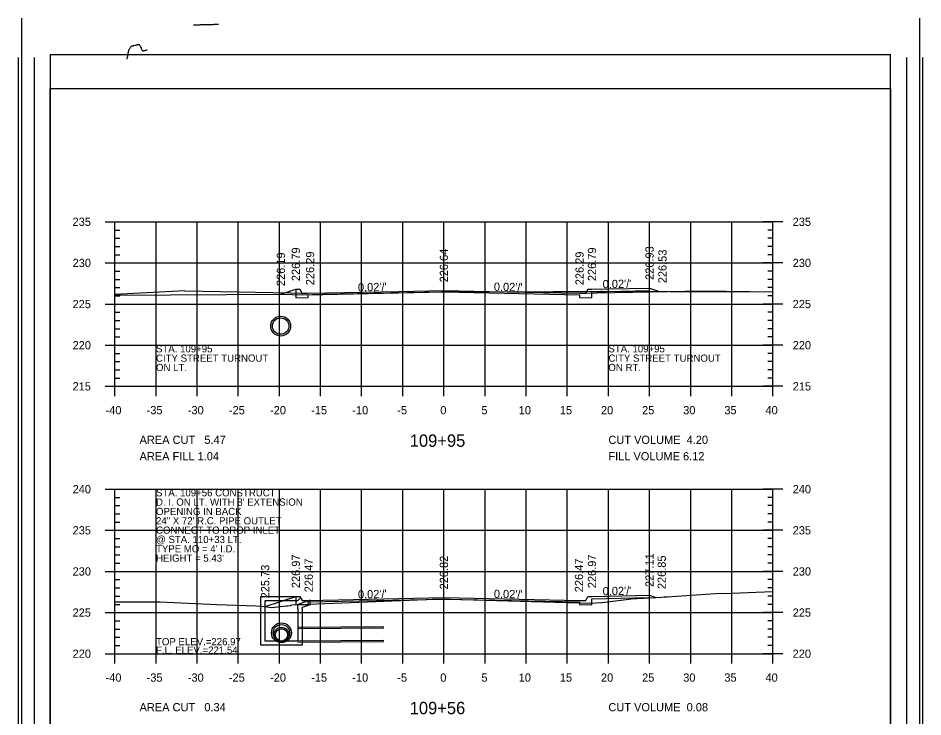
# Model space of a CAD drawing. Extents: x 1367903 to 1373764, y 376865 to 382130.
# Drawn here: x 1372116.6 to 1372336.6, y 377450.5 to 377620.4 of the extents above; entities that cross this region are included whole.
import ezdxf

# ---------------------------------------------------------------- set-up
doc = ezdxf.new("R2010")
doc.units = 0
for name, color, linetype in [('R_Axis', 7, 'Continuous'), ('R_Axis Annot', 7, 'Continuous'), ('R_Border', 7, 'Continuous'), ('R_Border PE', 7, 'Continuous'), ('R_Draft', 7, 'Continuous'), ('R_Drive', 7, 'Continuous'), ('R_Exist Surface', 7, 'Continuous'), ('R_Fin Surface', 7, 'Continuous'), ('R_Fin Surface Annot', 7, 'Continuous'), ('R_Grid', 7, 'Continuous'), ('R_Water', 7, 'Continuous'), ('R_Water Annot', 7, 'Continuous')]:
    doc.layers.add(name, color=color, linetype=linetype)

msp = doc.modelspace()

# ---------------------------------------------------------------- linework, layer by layer
for p, q in [((1372175.66, 377479.78), (1372185.16, 377479.78)), ((1372175.66, 377476.78), (1372175.66, 377479.78)), ((1372176.66, 377476.78), (1372176.66, 377478.78)), ((1372176.66, 377478.78), (1372184.66, 377478.78)), ((1372185.32, 377479.45), (1372184.66, 377478.78)), ((1372187.66, 377478.82), (1372184.66, 377477.78)), ((1372185.32, 377479.45), (1372185.16, 377479.78)), ((1372184.66, 377476.78), (1372184.66, 377477.78)), ((1372187.66, 377477.76), (1372185.66, 377477.07)), ((1372185.66, 377476.78), (1372185.66, 377477.07))]:
    msp.add_line(p, q)
for points in [[(1372184.16, 377554.42), (1372184.16, 377553.75), (1372184.16, 377553.75), (1372184.16, 377552.39), (1372187.16, 377552.45), (1372187.16, 377553.12), (1372220.16, 377553.78), (1372253.16, 377553.12), (1372253.16, 377552.45), (1372256.16, 377552.39), (1372256.16, 377553.83), (1372270.16, 377554.11), (1372270.16, 377554.7)], [(1372184.16, 377479.78), (1372184.16, 377479.11), (1372184.16, 377479.11), (1372184.16, 377477.75), (1372187.16, 377477.81), (1372187.16, 377478.47), (1372220.16, 377479.13), (1372253.16, 377478.47), (1372253.16, 377477.81), (1372256.16, 377477.75), (1372256.16, 377479.19), (1372270.16, 377479.47), (1372270.16, 377480.06)], [(1372187.66, 377477.76), (1372187.66, 377478.82)]]:
    msp.add_lwpolyline(points)
at = {"layer": 'R_Axis'}
for p, q in [((1372137.76, 377570.84), (1372142.56, 377570.84)), ((1372140.16, 377530.84), (1372140.16, 377570.84)), ((1372302.56, 377570.84), (1372297.76, 377570.84)), ((1372300.16, 377530.84), (1372300.16, 377570.84)), ((1372140.16, 377568.84), (1372141.36, 377568.84)), ((1372140.16, 377566.84), (1372141.36, 377566.84)), ((1372300.16, 377568.84), (1372298.96, 377568.84)), ((1372300.16, 377566.84), (1372298.96, 377566.84)), ((1372140.16, 377564.84), (1372141.36, 377564.84)), ((1372300.16, 377564.84), (1372298.96, 377564.84)), ((1372140.16, 377562.84), (1372141.36, 377562.84)), ((1372300.16, 377562.84), (1372298.96, 377562.84)), ((1372137.76, 377560.84), (1372142.56, 377560.84)), ((1372302.56, 377560.84), (1372297.76, 377560.84)), ((1372140.16, 377558.84), (1372141.36, 377558.84)), ((1372300.16, 377558.84), (1372298.96, 377558.84)), ((1372140.16, 377556.84), (1372141.36, 377556.84)), ((1372300.16, 377556.84), (1372298.96, 377556.84)), ((1372140.16, 377554.84), (1372141.36, 377554.84)), ((1372300.16, 377554.84), (1372298.96, 377554.84)), ((1372140.16, 377552.84), (1372141.36, 377552.84)), ((1372300.16, 377552.84), (1372298.96, 377552.84)), ((1372137.76, 377550.84), (1372142.56, 377550.84)), ((1372302.56, 377550.84), (1372297.76, 377550.84)), ((1372140.16, 377548.84), (1372141.36, 377548.84)), ((1372300.16, 377548.84), (1372298.96, 377548.84)), ((1372140.16, 377546.84), (1372141.36, 377546.84)), ((1372140.16, 377544.84), (1372141.36, 377544.84)), ((1372300.16, 377546.84), (1372298.96, 377546.84)), ((1372300.16, 377544.84), (1372298.96, 377544.84)), ((1372140.16, 377542.84), (1372141.36, 377542.84)), ((1372300.16, 377542.84), (1372298.96, 377542.84)), ((1372137.76, 377540.84), (1372142.56, 377540.84)), ((1372302.56, 377540.84), (1372297.76, 377540.84)), ((1372140.16, 377538.84), (1372141.36, 377538.84)), ((1372300.16, 377538.84), (1372298.96, 377538.84)), ((1372140.16, 377536.84), (1372141.36, 377536.84)), ((1372300.16, 377536.84), (1372298.96, 377536.84)), ((1372140.16, 377534.84), (1372141.36, 377534.84)), ((1372300.16, 377534.84), (1372298.96, 377534.84)), ((1372140.16, 377528.44), (1372140.16, 377533.24)), ((1372140.16, 377532.84), (1372141.36, 377532.84)), ((1372150.16, 377528.44), (1372150.16, 377533.24)), ((1372160.16, 377528.44), (1372160.16, 377533.24)), ((1372170.16, 377528.44), (1372170.16, 377533.24)), ((1372180.16, 377528.44), (1372180.16, 377533.24)), ((1372190.16, 377528.44), (1372190.16, 377533.24)), ((1372200.16, 377528.44), (1372200.16, 377533.24)), ((1372210.16, 377528.44), (1372210.16, 377533.24)), ((1372220.16, 377528.44), (1372220.16, 377533.24)), ((1372230.16, 377528.44), (1372230.16, 377533.24)), ((1372240.16, 377528.44), (1372240.16, 377533.24)), ((1372250.16, 377528.44), (1372250.16, 377533.24)), ((1372260.16, 377528.44), (1372260.16, 377533.24)), ((1372270.16, 377528.44), (1372270.16, 377533.24)), ((1372280.16, 377528.44), (1372280.16, 377533.24)), ((1372290.16, 377528.44), (1372290.16, 377533.24)), ((1372300.16, 377532.84), (1372298.96, 377532.84)), ((1372300.16, 377528.44), (1372300.16, 377533.24)), ((1372137.76, 377530.84), (1372142.56, 377530.84)), ((1372140.16, 377530.84), (1372300.16, 377530.84)), ((1372302.56, 377530.84), (1372297.76, 377530.84)), ((1372137.76, 377505.84), (1372142.56, 377505.84)), ((1372140.16, 377465.84), (1372140.16, 377505.84)), ((1372302.56, 377505.84), (1372297.76, 377505.84)), ((1372300.16, 377465.84), (1372300.16, 377505.84)), ((1372140.16, 377503.84), (1372141.36, 377503.84)), ((1372300.16, 377503.84), (1372298.96, 377503.84)), ((1372140.16, 377501.84), (1372141.36, 377501.84)), ((1372300.16, 377501.84), (1372298.96, 377501.84)), ((1372140.16, 377499.84), (1372141.36, 377499.84)), ((1372300.16, 377499.84), (1372298.96, 377499.84)), ((1372140.16, 377497.84), (1372141.36, 377497.84)), ((1372300.16, 377497.84), (1372298.96, 377497.84)), ((1372137.76, 377495.84), (1372142.56, 377495.84)), ((1372302.56, 377495.84), (1372297.76, 377495.84)), ((1372140.16, 377493.84), (1372141.36, 377493.84)), ((1372300.16, 377493.84), (1372298.96, 377493.84)), ((1372140.16, 377491.84), (1372141.36, 377491.84)), ((1372140.16, 377489.84), (1372141.36, 377489.84)), ((1372300.16, 377491.84), (1372298.96, 377491.84)), ((1372300.16, 377489.84), (1372298.96, 377489.84)), ((1372140.16, 377487.84), (1372141.36, 377487.84)), ((1372300.16, 377487.84), (1372298.96, 377487.84)), ((1372137.76, 377485.84), (1372142.56, 377485.84)), ((1372302.56, 377485.84), (1372297.76, 377485.84)), ((1372140.16, 377483.84), (1372141.36, 377483.84)), ((1372300.16, 377483.84), (1372298.96, 377483.84)), ((1372140.16, 377481.84), (1372141.36, 377481.84)), ((1372300.16, 377481.84), (1372298.96, 377481.84)), ((1372140.16, 377479.84), (1372141.36, 377479.84)), ((1372300.16, 377479.84), (1372298.96, 377479.84)), ((1372140.16, 377477.84), (1372141.36, 377477.84)), ((1372300.16, 377477.84), (1372298.96, 377477.84)), ((1372137.76, 377475.84), (1372142.56, 377475.84)), ((1372302.56, 377475.84), (1372297.76, 377475.84)), ((1372140.16, 377473.84), (1372141.36, 377473.84)), ((1372300.16, 377473.84), (1372298.96, 377473.84)), ((1372140.16, 377471.84), (1372141.36, 377471.84)), ((1372300.16, 377471.84), (1372298.96, 377471.84)), ((1372140.16, 377469.84), (1372141.36, 377469.84)), ((1372140.16, 377463.44), (1372140.16, 377468.24)), ((1372140.16, 377467.84), (1372141.36, 377467.84)), ((1372150.16, 377463.44), (1372150.16, 377468.24)), ((1372160.16, 377463.44), (1372160.16, 377468.24)), ((1372170.16, 377463.44), (1372170.16, 377468.24)), ((1372180.16, 377463.44), (1372180.16, 377468.24)), ((1372190.16, 377463.44), (1372190.16, 377468.24)), ((1372200.16, 377463.44), (1372200.16, 377468.24)), ((1372210.16, 377463.44), (1372210.16, 377468.24)), ((1372220.16, 377463.44), (1372220.16, 377468.24)), ((1372230.16, 377463.44), (1372230.16, 377468.24)), ((1372240.16, 377463.44), (1372240.16, 377468.24)), ((1372250.16, 377463.44), (1372250.16, 377468.24)), ((1372260.16, 377463.44), (1372260.16, 377468.24)), ((1372270.16, 377463.44), (1372270.16, 377468.24)), ((1372280.16, 377463.44), (1372280.16, 377468.24)), ((1372290.16, 377463.44), (1372290.16, 377468.24)), ((1372300.16, 377469.84), (1372298.96, 377469.84)), ((1372300.16, 377467.84), (1372298.96, 377467.84)), ((1372300.16, 377463.44), (1372300.16, 377468.24)), ((1372137.76, 377465.84), (1372142.56, 377465.84)), ((1372140.16, 377465.84), (1372300.16, 377465.84)), ((1372302.56, 377465.84), (1372297.76, 377465.84))]:
    msp.add_line(p, q, dxfattribs=at)
at = {"layer": 'R_Border'}
for p, q in [((1372117.43, 377620.35), (1372117.43, 377279.12)), ((1372335.82, 377620.35), (1372335.82, 377279.12)), ((1372124.46, 377611.47), (1372328.78, 377611.47)), ((1372124.46, 377611.47), (1372124.46, 377280.59)), ((1372328.78, 377280.59), (1372328.78, 377611.47))]:
    msp.add_line(p, q, dxfattribs=at)
at = {"layer": 'R_Border PE'}
for p, q in [((1372116.63, 377610.76), (1372116.63, 377288.8)), ((1372120.54, 377610.76), (1372120.54, 377288.8)), ((1372332.71, 377288.8), (1372332.71, 377610.76)), ((1372336.63, 377288.8), (1372336.63, 377610.76)), ((1372124.46, 377603.25), (1372328.78, 377603.25)), ((1372124.46, 377288.8), (1372124.46, 377603.25)), ((1372328.78, 377603.25), (1372328.78, 377288.8))]:
    msp.add_line(p, q, dxfattribs=at)
for points in [[(1372161.32, 377618.69), (1372161.26, 377618.69), (1372160.99, 377618.68), (1372160.86, 377618.68), (1372160.79, 377618.67), (1372160.63, 377618.67), (1372160.27, 377618.66), (1372159.94, 377618.65), (1372159.31, 377618.63)], [(1372161.77, 377618.7), (1372161.32, 377618.69)], [(1372165.33, 377618.79), (1372164.99, 377618.78), (1372164.79, 377618.78), (1372164.63, 377618.77), (1372164.4, 377618.76), (1372164.24, 377618.76), (1372164.05, 377618.75), (1372163.8, 377618.75), (1372163.61, 377618.74), (1372163.33, 377618.73), (1372163.23, 377618.73), (1372163.18, 377618.73), (1372162.96, 377618.72), (1372162.85, 377618.72), (1372162.63, 377618.71), (1372162.55, 377618.72), (1372162.13, 377618.7), (1372161.88, 377618.7), (1372161.77, 377618.7)], [(1372148.02, 377612.54), (1372148, 377612.55), (1372147.98, 377612.55), (1372147.96, 377612.55), (1372147.94, 377612.55), (1372147.91, 377612.55), (1372147.88, 377612.55), (1372147.86, 377612.55), (1372147.72, 377612.51), (1372147.6, 377612.48), (1372147.33, 377612.41), (1372147.11, 377612.36), (1372147.09, 377612.35), (1372147.07, 377612.35), (1372147.04, 377612.34), (1372147.03, 377612.34), (1372147.02, 377612.35), (1372147, 377612.35), (1372146.98, 377612.36), (1372146.95, 377612.38), (1372146.93, 377612.39), (1372146.91, 377612.4), (1372146.9, 377612.42), (1372146.88, 377612.45), (1372146.87, 377612.47), (1372146.85, 377612.5), (1372146.83, 377612.55), (1372146.73, 377612.76), (1372146.62, 377613), (1372146.52, 377613.23), (1372146.51, 377613.26), (1372146.5, 377613.28), (1372146.46, 377613.34), (1372146.43, 377613.39), (1372146.31, 377613.57), (1372146.23, 377613.69), (1372146.2, 377613.74), (1372146.18, 377613.76), (1372146.17, 377613.78), (1372146.14, 377613.81), (1372146.13, 377613.83), (1372146.11, 377613.84), (1372146.1, 377613.85), (1372146.07, 377613.87), (1372146.06, 377613.87), (1372146.03, 377613.88), (1372146, 377613.88), (1372145.99, 377613.88), (1372145.95, 377613.88), (1372145.84, 377613.86), (1372145.67, 377613.82), (1372145.48, 377613.77), (1372145.33, 377613.74), (1372145.23, 377613.72), (1372145.09, 377613.69), (1372144.97, 377613.66), (1372144.79, 377613.63), (1372144.57, 377613.58), (1372144.52, 377613.57), (1372144.4, 377613.54), (1372144.29, 377613.52), (1372144.25, 377613.51), (1372144.22, 377613.5), (1372144.2, 377613.5), (1372144.18, 377613.49), (1372144.17, 377613.49), (1372144.15, 377613.47), (1372144.13, 377613.46), (1372144.11, 377613.44), (1372144.08, 377613.42), (1372144.05, 377613.39), (1372144.03, 377613.35), (1372144, 377613.31), (1372143.96, 377613.26), (1372143.9, 377613.16), (1372143.8, 377613.02), (1372143.72, 377612.89), (1372143.63, 377612.75), (1372143.58, 377612.67), (1372143.54, 377612.62), (1372143.5, 377612.55), (1372143.49, 377612.54), (1372143.48, 377612.52), (1372143.47, 377612.5), (1372143.47, 377612.48), (1372143.46, 377612.46), (1372143.46, 377612.44), (1372143.45, 377612.42), (1372143.44, 377612.39), (1372143.44, 377612.37), (1372143.43, 377612.35), (1372143.43, 377612.33), (1372143.41, 377612.24), (1372143.37, 377612), (1372143.33, 377611.76), (1372143.31, 377611.65), (1372143.22, 377611.18), (1372143.2, 377611.04), (1372143.16, 377610.84), (1372143.1, 377610.54), (1372143.07, 377610.39)]]:
    msp.add_lwpolyline(points, dxfattribs=at)
at = {"layer": 'R_Drive'}
for p, q in [((1372157.16, 377554.05), (1372140.16, 377553.17)), ((1372157.16, 377554.05), (1372187.16, 377553.45)), ((1372253.16, 377553.45), (1372283.15, 377554.05)), ((1372283.15, 377554.05), (1372300.16, 377553.83))]:
    msp.add_line(p, q, dxfattribs=at)
at = {"layer": 'R_Exist Surface'}
for points in [[(1372140.16, 377553.03), (1372180.83, 377553.21), (1372181.09, 377553.22), (1372185.43, 377553.11), (1372190.86, 377553.25), (1372219.5, 377553.83), (1372220, 377553.84), (1372220.29, 377553.84), (1372246.83, 377553.86), (1372254.98, 377553.87), (1372254.98, 377553.87), (1372255.01, 377553.87), (1372258.35, 377553.95), (1372258.46, 377553.95), (1372258.54, 377553.94), (1372275.18, 377553.89), (1372300.16, 377553.8)], [(1372140.16, 377478.42), (1372142.21, 377478.42), (1372151.12, 377478.47), (1372164.96, 377477.84), (1372174.4, 377477.45), (1372175.86, 377477.39), (1372178.22, 377477.1), (1372181.85, 377477.45), (1372182.14, 377477.46), (1372182.86, 377477.52), (1372183.2, 377477.71), (1372215.73, 377479.05), (1372218.67, 377479.2), (1372221.75, 377479.1), (1372255.67, 377478.09), (1372258.48, 377478.32), (1372258.67, 377478.31), (1372265.09, 377479.07), (1372265.71, 377479.17), (1372273.15, 377479.62), (1372273.73, 377479.66), (1372274.42, 377479.69), (1372286.21, 377480.45), (1372290.1, 377480.53), (1372300.16, 377480.99)]]:
    msp.add_lwpolyline(points, dxfattribs=at)
at = {"layer": 'R_Fin Surface'}
for points in [[(1372180.51, 377553.21), (1372184.16, 377554.42), (1372185.16, 377554.42), (1372185.66, 377553.42), (1372187.16, 377553.45), (1372209.16, 377553.89), (1372220.16, 377554.11), (1372231.16, 377553.89), (1372253.16, 377553.45), (1372254.66, 377553.42), (1372255.16, 377554.42), (1372256.16, 377554.42), (1372260.16, 377554.5), (1372270.16, 377554.7), (1372272.56, 377553.9)], [(1372176.7, 377477.29), (1372184.16, 377479.78), (1372185.16, 377479.78), (1372185.66, 377478.78), (1372187.16, 377478.81), (1372209.16, 377479.25), (1372220.16, 377479.47), (1372231.16, 377479.25), (1372253.16, 377478.81), (1372254.66, 377478.78), (1372255.16, 377479.78), (1372256.16, 377479.78), (1372260.16, 377479.86), (1372270.16, 377480.06), (1372271.72, 377479.54)]]:
    msp.add_lwpolyline(points, dxfattribs=at)
at = {"layer": 'R_Grid'}
for p, q in [((1372140.16, 377570.84), (1372300.16, 377570.84)), ((1372140.16, 377530.84), (1372140.16, 377570.84)), ((1372150.16, 377530.84), (1372150.16, 377570.84)), ((1372160.16, 377530.84), (1372160.16, 377570.84)), ((1372170.16, 377530.84), (1372170.16, 377570.84)), ((1372180.16, 377530.84), (1372180.16, 377570.84)), ((1372190.16, 377530.84), (1372190.16, 377570.84)), ((1372200.16, 377530.84), (1372200.16, 377570.84)), ((1372210.16, 377530.84), (1372210.16, 377570.84)), ((1372220.16, 377530.84), (1372220.16, 377570.84)), ((1372230.16, 377530.84), (1372230.16, 377570.84)), ((1372240.16, 377530.84), (1372240.16, 377570.84)), ((1372250.16, 377530.84), (1372250.16, 377570.84)), ((1372260.16, 377530.84), (1372260.16, 377570.84)), ((1372270.16, 377530.84), (1372270.16, 377570.84)), ((1372280.16, 377530.84), (1372280.16, 377570.84)), ((1372290.16, 377530.84), (1372290.16, 377570.84)), ((1372300.16, 377530.84), (1372300.16, 377570.84)), ((1372140.16, 377560.84), (1372300.16, 377560.84)), ((1372140.16, 377550.84), (1372300.16, 377550.84)), ((1372140.16, 377540.84), (1372300.16, 377540.84)), ((1372140.16, 377530.84), (1372300.16, 377530.84)), ((1372140.16, 377505.84), (1372300.16, 377505.84)), ((1372140.16, 377465.84), (1372140.16, 377505.84)), ((1372150.16, 377465.84), (1372150.16, 377505.84)), ((1372160.16, 377465.84), (1372160.16, 377505.84)), ((1372170.16, 377465.84), (1372170.16, 377505.84)), ((1372180.16, 377465.84), (1372180.16, 377505.84)), ((1372190.16, 377465.84), (1372190.16, 377505.84)), ((1372200.16, 377465.84), (1372200.16, 377505.84)), ((1372210.16, 377465.84), (1372210.16, 377505.84)), ((1372220.16, 377465.84), (1372220.16, 377505.84)), ((1372230.16, 377465.84), (1372230.16, 377505.84)), ((1372240.16, 377465.84), (1372240.16, 377505.84)), ((1372250.16, 377465.84), (1372250.16, 377505.84)), ((1372260.16, 377465.84), (1372260.16, 377505.84)), ((1372270.16, 377465.84), (1372270.16, 377505.84)), ((1372280.16, 377465.84), (1372280.16, 377505.84)), ((1372290.16, 377465.84), (1372290.16, 377505.84)), ((1372300.16, 377465.84), (1372300.16, 377505.84)), ((1372140.16, 377495.84), (1372300.16, 377495.84)), ((1372140.16, 377485.84), (1372300.16, 377485.84)), ((1372140.16, 377475.84), (1372300.16, 377475.84)), ((1372140.16, 377465.84), (1372300.16, 377465.84))]:
    msp.add_line(p, q, dxfattribs=at)
at = {"layer": 'R_Water'}
for p, q in [((1372180.48, 377547.92), (1372180.48, 377547.87)), ((1372180.48, 377547.5), (1372180.48, 377547.45)), ((1372180.48, 377543.5), (1372180.48, 377543.45)), ((1372180.48, 377543.08), (1372180.48, 377543.03)), ((1372205.54, 377472.38), (1372184.61, 377472.25)), ((1372205.54, 377472.04), (1372184.61, 377471.92)), ((1372205.54, 377469.04), (1372184.61, 377468.92)), ((1372205.54, 377468.71), (1372184.61, 377468.58))]:
    msp.add_line(p, q, dxfattribs=at)
for points in [[(1372185.66, 377476.78), (1372185.66, 377467.92), (1372180.66, 377467.92), (1372175.66, 377467.92), (1372175.66, 377476.78)], [(1372184.66, 377476.78), (1372184.66, 377468.92), (1372180.66, 377468.92), (1372176.66, 377468.92), (1372176.66, 377476.78)]]:
    msp.add_lwpolyline(points, dxfattribs=at)
for centre, radius in [((1372180.48, 377545.48), 2.42), ((1372180.48, 377545.48), 2), ((1372180.66, 377470.92), 2.42), ((1372180.66, 377470.92), 2), ((1372180.66, 377470.42), 1.83), ((1372180.66, 377470.42), 1.5)]:
    msp.add_circle(centre, radius, dxfattribs=at)

# ---------------------------------------------------------------- texts
at = {"layer": 'R_Axis Annot'}
for s, height, p in [('235', 2, (1372129.87, 377569.84)), ('235', 2, (1372304.96, 377569.84)), ('230', 2, (1372129.88, 377559.84)), ('230', 2, (1372304.96, 377559.84)), ('225', 2, (1372129.87, 377549.84)), ('225', 2, (1372304.96, 377549.84)), ('220', 2, (1372129.88, 377539.84)), ('220', 2, (1372304.96, 377539.84)), ('215', 2, (1372129.87, 377529.84)), ('215', 2, (1372304.96, 377529.84)), ('-40', 2, (1372137.89, 377524.04)), ('-35', 2, (1372147.88, 377524.04)), ('-30', 2, (1372157.89, 377524.04)), ('-25', 2, (1372167.88, 377524.04)), ('-20', 2, (1372177.89, 377524.04)), ('-15', 2, (1372187.88, 377524.04)), ('-10', 2, (1372197.89, 377524.04)), ('-5', 2, (1372208.82, 377524.04)), ('0', 2, (1372219.28, 377524.04)), ('5', 2, (1372229.28, 377524.04)), ('10', 2, (1372238.35, 377524.04)), ('15', 2, (1372248.35, 377524.04)), ('20', 2, (1372258.35, 377524.04)), ('25', 2, (1372268.35, 377524.04)), ('30', 2, (1372278.35, 377524.04)), ('35', 2, (1372288.35, 377524.04)), ('40', 2, (1372298.35, 377524.04)), ('AREA CUT   5.47', 2, (1372146.16, 377516.84)), ('109+95', 3, (1372211.86, 377516.14)), ('CUT VOLUME  4.20', 2, (1372260.16, 377516.84)), ('AREA FILL 1.04', 2, (1372146.16, 377512.84)), ('FILL VOLUME 6.12', 2, (1372260.16, 377512.84)), ('240', 2, (1372129.88, 377504.84)), ('240', 2, (1372304.96, 377504.84)), ('235', 2, (1372129.87, 377494.84)), ('235', 2, (1372304.96, 377494.84)), ('230', 2, (1372129.88, 377484.84)), ('230', 2, (1372304.96, 377484.84)), ('225', 2, (1372129.87, 377474.84)), ('225', 2, (1372304.96, 377474.84)), ('220', 2, (1372129.88, 377464.84)), ('220', 2, (1372304.96, 377464.84)), ('-40', 2, (1372137.89, 377459.04)), ('-35', 2, (1372147.88, 377459.04)), ('-30', 2, (1372157.89, 377459.04)), ('-25', 2, (1372167.88, 377459.04)), ('-20', 2, (1372177.89, 377459.04)), ('-15', 2, (1372187.88, 377459.04)), ('-10', 2, (1372197.89, 377459.04)), ('-5', 2, (1372208.82, 377459.04)), ('0', 2, (1372219.28, 377459.04)), ('5', 2, (1372229.28, 377459.04)), ('10', 2, (1372238.35, 377459.04)), ('15', 2, (1372248.35, 377459.04)), ('20', 2, (1372258.35, 377459.04)), ('25', 2, (1372268.35, 377459.04)), ('30', 2, (1372278.35, 377459.04)), ('35', 2, (1372288.35, 377459.04)), ('40', 2, (1372298.35, 377459.04)), ('AREA CUT   0.34', 2, (1372146.16, 377451.84)), ('109+56', 3, (1372211.85, 377451.14)), ('CUT VOLUME  0.08', 2, (1372260.16, 377451.84))]:
    msp.add_text(s, height=height, dxfattribs=at).set_placement(p)
at = {"layer": 'R_Draft'}
for s, p in [('STA. 109+95', (1372150.16, 377539.09)), ('STA. 109+95', (1372260.16, 377539.09)), ('CITY STREET TURNOUT', (1372150.16, 377536.82)), ('CITY STREET TURNOUT', (1372260.16, 377536.82)), ('ON LT.', (1372150.16, 377534.55)), ('ON RT.', (1372260.16, 377534.55)), ('STA. 109+56 CONSTRUCT', (1372150.16, 377504.09)), ("D. I. ON LT. WITH 8' EXTENSION", (1372150.16, 377501.82)), ('OPENING IN BACK', (1372150.16, 377499.55)), ('24" X 72\' R.C. PIPE OUTLET', (1372150.16, 377497.28)), ('CONNECT TO DROP INLET', (1372150.16, 377495.01)), ('@ STA. 110+33 LT.', (1372150.16, 377492.74)), ("TYPE MO = 4' I.D.", (1372150.16, 377490.47)), ("HEIGHT = 5.43'", (1372150.16, 377488.2))]:
    msp.add_text(s, height=1.75, dxfattribs=at).set_placement(p)
at = {"layer": 'R_Fin Surface Annot'}
for s, rotation, p in [('226.93', 90, (1372271.16, 377556.7)), ('226.19', 90, (1372181.51, 377555.21)), ('226.79', 90, (1372185.16, 377556.42)), ('226.29', 90, (1372188.62, 377555.42)), ('226.64', 90, (1372221.16, 377556.11)), ('226.29', 90, (1372254.14, 377555.42)), ('226.79', 90, (1372257.16, 377556.42)), ('226.53', 90, (1372274.3, 377555.9)), ("0.02'/'", 1.1459, (1372199.28, 377553.89)), ("0.02'/'", 358.8544, (1372232.29, 377554.07)), ("0.02'/'", 1.1459, (1372258.78, 377554.67)), ('226.97', 90, (1372185.16, 377481.78)), ('226.97', 90, (1372257.16, 377481.78)), ('227.11', 90, (1372271.16, 377482.06)), ('226.47', 90, (1372188.28, 377480.78)), ('226.82', 90, (1372221.16, 377481.47)), ('226.47', 90, (1372254.01, 377480.78)), ('226.85', 90, (1372274.12, 377481.54)), ('225.73', 90, (1372177.7, 377479.29)), ("0.02'/'", 1.1459, (1372199.28, 377479.25)), ("0.02'/'", 358.8544, (1372232.29, 377479.42)), ("0.02'/'", 1.1459, (1372258.78, 377480.03))]:
    msp.add_text(s, height=2, rotation=rotation, dxfattribs=at).set_placement(p)
at = {"layer": 'R_Water Annot'}
for s, p in [('TOP ELEV.=226.97', (1372150.16, 377467.89)), ('F.L. ELEV.=221.54', (1372150.16, 377465.84))]:
    msp.add_text(s, height=1.75, dxfattribs=at).set_placement(p)

doc.saveas('drawing.dxf')
